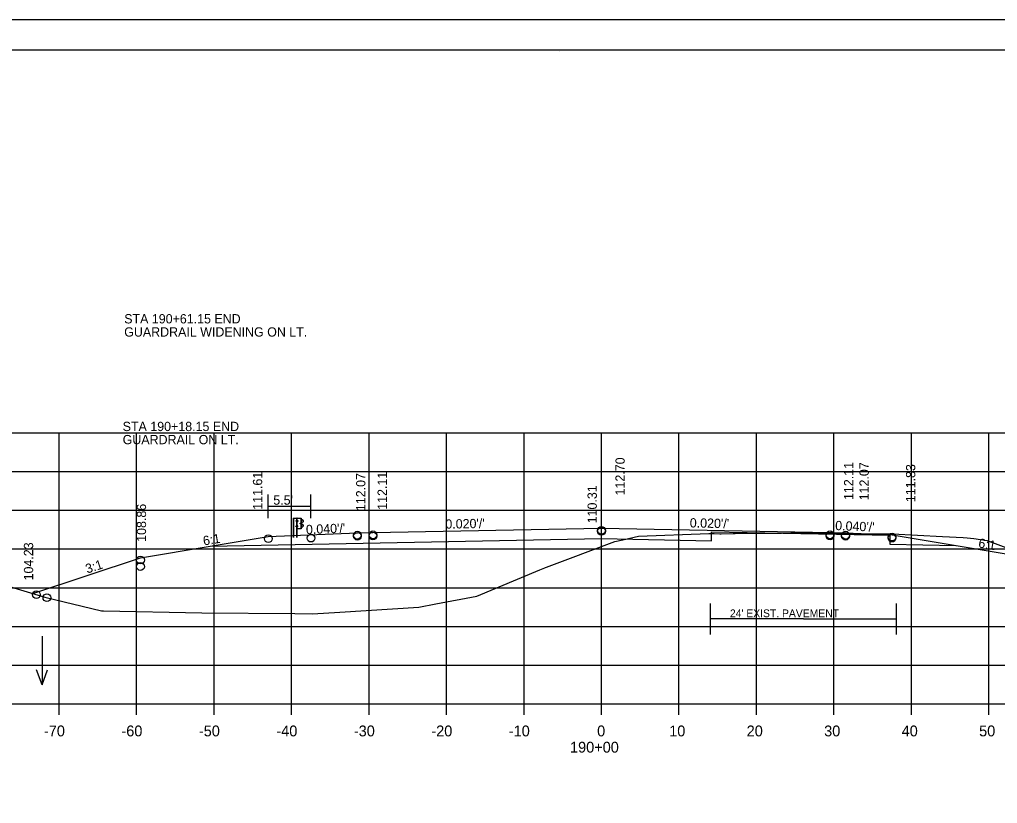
# Model space of a CAD drawing. Extents: x 1175611 to 1176402, y -433344 to -416213.
# Drawn here: x 1175705.9 to 1175832.1, y -426191.3 to -426090 of the extents above; entities that cross this region are included whole.
import ezdxf

# ---------------------------------------------------------------- set-up
doc = ezdxf.new("R2010")
doc.units = 0
for name, color, linetype in [('R_Alt Surface', 7, 'Continuous'), ('R_Axis', 7, 'Continuous'), ('R_Axis Annot', 7, 'Continuous'), ('R_Border', 7, 'Continuous'), ('R_Exist Surface', 7, 'Continuous'), ('R_Fin Surface', 7, 'Continuous'), ('R_Grid', 7, 'Continuous'), ('R_No Plot', 7, 'Continuous'), ('R_Proposed Road', 7, 'Continuous'), ('R_Water Annot', 7, 'Continuous'), ('R_Xsect Elev', 7, 'Continuous'), ('R_Xsect Slope', 7, 'Continuous')]:
    doc.layers.add(name, color=color, linetype=linetype)

msp = doc.modelspace()

# ---------------------------------------------------------------- linework, layer by layer
at = {"layer": 'R_Alt Surface'}
for p, q in [((1175737.97, -426154.41), (1175737.97, -426151.39)), ((1175743.47, -426154.42), (1175743.47, -426151.39)), ((1175743.47, -426152.91), (1175737.97, -426152.91)), ((1175807.04, -426167.43), (1175795.04, -426167.43)), ((1175807.04, -426167.43), (1175819.04, -426167.43))]:
    msp.add_line(p, q, dxfattribs=at)
for points in [[(1175730.47, -426158.04), (1175780.97, -426157.03), (1175780.97, -426157.03), (1175795.15, -426157.34), (1175795.15, -426156.17), (1175818.19, -426156.61), (1175818.2, -426157.77), (1175826.72, -426157.94)], [(1175795.04, -426169.43), (1175795.04, -426165.43)], [(1175819.04, -426169.43), (1175819.04, -426165.43)]]:
    msp.add_lwpolyline(points, dxfattribs=at)
at = {"layer": 'R_Axis'}
for p, q in [((1175640.97, -426178.4), (1175920.97, -426178.4)), ((1175710.97, -426179.8), (1175710.97, -426178.4)), ((1175720.97, -426179.8), (1175720.97, -426178.4)), ((1175730.97, -426179.8), (1175730.97, -426178.4)), ((1175740.97, -426179.8), (1175740.97, -426178.4)), ((1175750.97, -426179.8), (1175750.97, -426178.4)), ((1175760.97, -426179.8), (1175760.97, -426178.4)), ((1175770.97, -426179.8), (1175770.97, -426178.4)), ((1175780.97, -426179.8), (1175780.97, -426178.4)), ((1175790.97, -426179.8), (1175790.97, -426178.4)), ((1175800.97, -426179.8), (1175800.97, -426178.4)), ((1175810.97, -426179.8), (1175810.97, -426178.4)), ((1175820.97, -426179.8), (1175820.97, -426178.4)), ((1175830.97, -426179.8), (1175830.97, -426178.4))]:
    msp.add_line(p, q, dxfattribs=at)
at = {"layer": 'R_Border'}
for p, q in [((1175622.97, -426093.94), (1175939.15, -426093.94)), ((1175775.49, -426094.2), (1175775.49, -426094.2)), ((1175775.49, -426094.2), (1175775.49, -426094.2))]:
    msp.add_line(p, q, dxfattribs=at)
at = {"layer": 'R_Exist Surface'}
msp.add_lwpolyline([(1175697.81, -426161.23), (1175709.12, -426164.63), (1175716.43, -426166.38), (1175716.5, -426166.4), (1175716.68, -426166.4), (1175729.38, -426166.64), (1175741.41, -426166.75), (1175743.69, -426166.77), (1175747.2, -426166.56), (1175757.39, -426165.93), (1175759.59, -426165.5), (1175764.87, -426164.5), (1175773.02, -426161.11), (1175773.68, -426160.83), (1175773.76, -426160.8), (1175773.88, -426160.76), (1175782.71, -426157.43), (1175783.72, -426157.22), (1175785.74, -426156.75), (1175794.84, -426156.42), (1175795.53, -426156.39), (1175796.26, -426156.45), (1175796.42, -426156.46), (1175797.96, -426156.42), (1175798.22, -426156.41), (1175800.11, -426156.37), (1175800.62, -426156.37), (1175803.87, -426156.35), (1175804.22, -426156.35), (1175805.42, -426156.31), (1175805.59, -426156.31), (1175806.83, -426156.32), (1175807.04, -426156.32), (1175808.36, -426156.34), (1175808.59, -426156.34), (1175808.89, -426156.35), (1175810.93, -426156.4), (1175811.23, -426156.4), (1175813.1, -426156.38), (1175813.52, -426156.39), (1175816.75, -426156.47), (1175817.02, -426156.47), (1175818.04, -426156.43), (1175818.19, -426156.43), (1175818.49, -426156.44), (1175818.54, -426156.45), (1175824.97, -426156.78), (1175827.64, -426156.93), (1175828.15, -426156.97), (1175829.03, -426157.06), (1175830.75, -426157.29), (1175835.71, -426159.15)], dxfattribs=at)
at = {"layer": 'R_Fin Surface'}
msp.add_lwpolyline([(1175707.58, -426164.17), (1175721.47, -426159.54), (1175730.45, -426158.04), (1175737.97, -426156.79), (1175749.47, -426156.33), (1175751.47, -426156.29), (1175780.97, -426155.7), (1175810.47, -426156.29), (1175812.47, -426156.33), (1175818.47, -426156.57), (1175826.75, -426157.95), (1175840.47, -426160.23), (1175849.92, -426163.38)], dxfattribs=at)
at = {"layer": 'R_Grid'}
for p, q in [((1175640.97, -426143.4), (1175920.97, -426143.4)), ((1175710.97, -426178.4), (1175710.97, -426143.4)), ((1175720.97, -426178.4), (1175720.97, -426143.4)), ((1175730.97, -426178.4), (1175730.97, -426143.4)), ((1175740.97, -426178.4), (1175740.97, -426143.4)), ((1175750.97, -426178.4), (1175750.97, -426143.4)), ((1175760.97, -426178.4), (1175760.97, -426143.4)), ((1175770.97, -426178.4), (1175770.97, -426143.4)), ((1175780.97, -426178.4), (1175780.97, -426143.4)), ((1175790.97, -426178.4), (1175790.97, -426143.4)), ((1175800.97, -426178.4), (1175800.97, -426143.4)), ((1175810.97, -426178.4), (1175810.97, -426143.4)), ((1175820.97, -426178.4), (1175820.97, -426143.4)), ((1175830.97, -426178.4), (1175830.97, -426143.4)), ((1175640.97, -426148.4), (1175920.97, -426148.4)), ((1175640.97, -426153.4), (1175920.97, -426153.4)), ((1175640.97, -426158.4), (1175920.97, -426158.4)), ((1175640.97, -426163.4), (1175920.97, -426163.4)), ((1175640.97, -426168.4), (1175920.97, -426168.4)), ((1175640.97, -426173.4), (1175920.97, -426173.4)), ((1175640.97, -426178.4), (1175920.97, -426178.4))]:
    msp.add_line(p, q, dxfattribs=at)
at = {"layer": 'R_No Plot'}
msp.add_line((1175610.57, -426090.04), (1175943.91, -426090.04), dxfattribs=at)
msp.add_lwpolyline([(1175610.57, -426090.04), (1175943.91, -426090.04), (1175943.91, -426303.38), (1175610.57, -426303.38)], close=True, dxfattribs=at)
for centre in [(1175780.97, -426155.99), (1175737.97, -426157.08), (1175743.47, -426157), (1175749.47, -426156.62), (1175749.47, -426156.76), (1175751.47, -426156.58), (1175751.47, -426156.72), (1175780.97, -426156.13), (1175810.47, -426156.58), (1175810.47, -426156.72), (1175812.47, -426156.62), (1175812.47, -426156.76), (1175818.47, -426156.86), (1175818.47, -426157), (1175721.47, -426159.83), (1175721.47, -426160.67), (1175708.04, -426164.3), (1175708.04, -426164.3), (1175709.39, -426164.69)]:
    msp.add_circle(centre, 0.5, dxfattribs=at)
at = {"layer": 'R_Proposed Road'}
for p, q in [((1175741.17, -426154.42), (1175741.17, -426156.94)), ((1175741.2, -426154.42), (1175741.2, -426156.94)), ((1175741.56, -426155.52), (1175741.56, -426155.43)), ((1175741.57, -426154.83), (1175741.57, -426154.74)), ((1175741.62, -426155.41), (1175741.57, -426155.41)), ((1175741.62, -426155.44), (1175741.57, -426155.44)), ((1175741.62, -426155.51), (1175741.57, -426155.51)), ((1175741.62, -426155.54), (1175741.57, -426155.54)), ((1175741.63, -426154.72), (1175741.58, -426154.72)), ((1175741.63, -426154.75), (1175741.58, -426154.75)), ((1175741.63, -426154.82), (1175741.58, -426154.82)), ((1175741.63, -426154.85), (1175741.58, -426154.85)), ((1175741.62, -426155.51), (1175741.58, -426155.51)), ((1175741.63, -426154.82), (1175741.59, -426154.82)), ((1175741.62, -426155.54), (1175741.62, -426155.41)), ((1175741.7, -426154.42), (1175741.63, -426154.42)), ((1175741.63, -426154.85), (1175741.63, -426154.72)), ((1175741.67, -426156.94), (1175741.67, -426154.42)), ((1175741.7, -426154.42), (1175741.69, -426154.42)), ((1175741.75, -426154.79), (1175741.7, -426154.79)), ((1175741.75, -426155.48), (1175741.7, -426155.48)), ((1175741.71, -426154.73), (1175741.76, -426154.73)), ((1175741.71, -426154.85), (1175741.76, -426154.85)), ((1175741.76, -426155.41), (1175741.71, -426155.41)), ((1175741.76, -426155.54), (1175741.71, -426155.54)), ((1175741.76, -426154.73), (1175741.76, -426154.85)), ((1175741.76, -426155.54), (1175741.76, -426155.41)), ((1175742.13, -426155.15), (1175742.13, -426155.06)), ((1175742.19, -426155.04), (1175742.14, -426155.04)), ((1175742.19, -426155.08), (1175742.14, -426155.08)), ((1175742.19, -426155.14), (1175742.14, -426155.14)), ((1175742.19, -426155.14), (1175742.14, -426155.14)), ((1175742.19, -426155.17), (1175742.14, -426155.17)), ((1175742.19, -426155.17), (1175742.19, -426155.04)), ((1175742.2, -426155.79), (1175742.2, -426154.43)), ((1175742.34, -426154.64), (1175742.23, -426154.58)), ((1175742.23, -426155.63), (1175742.33, -426155.57)), ((1175742.23, -426155.65), (1175742.35, -426155.59)), ((1175742.33, -426154.65), (1175742.24, -426154.6)), ((1175742.24, -426155.17), (1175742.24, -426155.04)), ((1175742.26, -426155.17), (1175742.26, -426155.04)), ((1175742.28, -426154.97), (1175742.46, -426154.86)), ((1175742.43, -426155.34), (1175742.28, -426155.24)), ((1175742.45, -426155.32), (1175742.29, -426155.22)), ((1175742.3, -426154.99), (1175742.47, -426154.88)), ((1175742.46, -426154.76), (1175742.33, -426154.65)), ((1175742.33, -426155.57), (1175742.46, -426155.46)), ((1175742.47, -426154.74), (1175742.34, -426154.64)), ((1175742.35, -426155.59), (1175742.47, -426155.48)), ((1175741.7, -426155.79), (1175741.66, -426155.79))]:
    msp.add_line(p, q, dxfattribs=at)
msp.add_lwpolyline([(1175741.17, -426154.42), (1175741.63, -426154.42), (1175741.63, -426156.94)], dxfattribs=at)
for points in [[(1175741.56, -426155.44), (1175741.56, -426155.51), (1175741.54, -426155.51), (1175741.54, -426155.44)], [(1175741.57, -426154.75), (1175741.57, -426154.82), (1175741.55, -426154.82), (1175741.55, -426154.75)], [(1175741.62, -426155.39), (1175741.62, -426155.56), (1175741.63, -426155.56), (1175741.63, -426155.39)], [(1175741.63, -426154.7), (1175741.63, -426154.87), (1175741.64, -426154.87), (1175741.64, -426154.7)], [(1175742.22, -426154.42), (1175742.22, -426155.79), (1175741.7, -426155.79), (1175741.7, -426154.42)], [(1175741.75, -426154.73), (1175741.75, -426154.85), (1175741.7, -426154.85), (1175741.7, -426154.73)], [(1175741.75, -426155.41), (1175741.75, -426155.54), (1175741.7, -426155.54), (1175741.7, -426155.41)], [(1175742.13, -426155.08), (1175742.13, -426155.14), (1175742.1, -426155.14), (1175742.1, -426155.08)], [(1175742.18, -426155.02), (1175742.18, -426155.19), (1175742.19, -426155.19), (1175742.19, -426155.02)]]:
    msp.add_lwpolyline(points, close=True, dxfattribs=at)
for centre, radius, start, end in [((1175741.59, -426155.43), 0.022, 134.5745, 222.2244), ((1175741.66, -426155.47), 0.0922, 159.7423, 200.2577), ((1175741.59, -426155.52), 0.025, 140.9334, 216.6234), ((1175741.6, -426154.74), 0.022, 134.5745, 222.2244), ((1175741.67, -426154.79), 0.0922, 159.7423, 200.2577), ((1175741.6, -426154.83), 0.025, 140.9334, 216.6234), ((1175742.15, -426155.06), 0.022, 134.5745, 222.2244), ((1175742.22, -426155.11), 0.0922, 159.7423, 200.2577), ((1175742.16, -426155.15), 0.025, 140.9334, 216.6234), ((1175742.33, -426155.04), 0.0865, 118.106, 175.0444), ((1175742.31, -426155.18), 0.0703, 171.7804, 246.8536), ((1175742.33, -426155.04), 0.0622, 118.106, 175.0444), ((1175742.26, -426155.11), 0.0453, 282.9554, 86.0697), ((1175742.31, -426155.18), 0.0462, 171.7804, 246.8536), ((1175742.39, -426155.41), 0.0854, 325.2184, 59.12), ((1175742.39, -426155.41), 0.109, 325.2184, 59.12), ((1175742.43, -426154.81), 0.062, 299.2499, 57.9783), ((1175742.43, -426154.81), 0.0856, 299.2499, 57.9783)]:
    msp.add_arc(centre, radius, start, end, dxfattribs=at)
at = {"layer": 'R_Water Annot'}
for p, q in [((1175708.77, -426169.66), (1175708.77, -426175.94)), ((1175708.77, -426175.94), (1175708.07, -426174.02)), ((1175708.77, -426175.94), (1175709.47, -426174.02))]:
    msp.add_line(p, q, dxfattribs=at)

# ---------------------------------------------------------------- texts
at = {"layer": 'R_Alt Surface'}
for s, height, p in [("5.5'", 1.2, (1175738.61, -426152.69)), ("24' EXIST. PAVEMENT", 1, (1175797.55, -426167.21))]:
    msp.add_text(s, height=height, dxfattribs=at).set_placement(p)
at = {"layer": 'R_Axis Annot'}
for s, p in [('-70', (1175709.01, -426182.6)), ('-60', (1175719.01, -426182.6)), ('-50', (1175729.01, -426182.6)), ('-40', (1175739.01, -426182.6)), ('-30', (1175749.01, -426182.6)), ('-20', (1175759.01, -426182.6)), ('-10', (1175769.01, -426182.6)), ('0', (1175780.41, -426182.6)), ('10', (1175789.71, -426182.6)), ('20', (1175799.71, -426182.6)), ('30', (1175809.71, -426182.6)), ('40', (1175819.71, -426182.6)), ('50', (1175829.71, -426182.6)), ('190+00', (1175776.91, -426184.7))]:
    msp.add_text(s, height=1.4, dxfattribs=at).set_placement(p)
at = {"layer": 'R_Water Annot'}
for s, p in [('STA 190+61.15 END', (1175719.37, -426129.28)), ('GUARDRAIL WIDENING ON LT.', (1175719.37, -426130.98)), ('STA 190+18.15 END', (1175719.17, -426143.18)), ('GUARDRAIL ON LT.', (1175719.17, -426144.88))]:
    msp.add_text(s, height=1.2, dxfattribs=at).set_placement(p)
at = {"layer": 'R_Xsect Elev'}
for s, p in [('112.70', (1175783.97, -426151.49)), ('112.11', (1175813.47, -426152.08)), ('112.07', (1175815.47, -426152.12)), ('111.83', (1175821.47, -426152.36)), ('111.61', (1175737.18, -426153.34)), ('112.07', (1175750.5, -426153.51)), ('112.11', (1175753.27, -426153.34)), ('110.31', (1175780.37, -426155.09)), ('108.86', (1175722.19, -426157.48)), ('104.23', (1175707.62, -426162.46))]:
    msp.add_text(s, height=1.2, rotation=90, dxfattribs=at).set_placement(p)
at = {"layer": 'R_Xsect Slope'}
for s, rotation, p in [("0.040'/'", 2.2906, (1175742.85, -426156.5)), ("0.020'/'", 1.1458, (1175760.83, -426155.79)), ("0.020'/'", 358.8542, (1175792.36, -426155.62)), ("0.040'/'", 357.7094, (1175811.12, -426155.96)), ('6:1', 9.4623, (1175729.64, -426157.96)), ('6:1', 350.5377, (1175829.55, -426158.2)), ('3:1', 18.4349, (1175714.6, -426161.59))]:
    msp.add_text(s, height=1.2, rotation=rotation, dxfattribs=at).set_placement(p)

doc.saveas('drawing.dxf')
